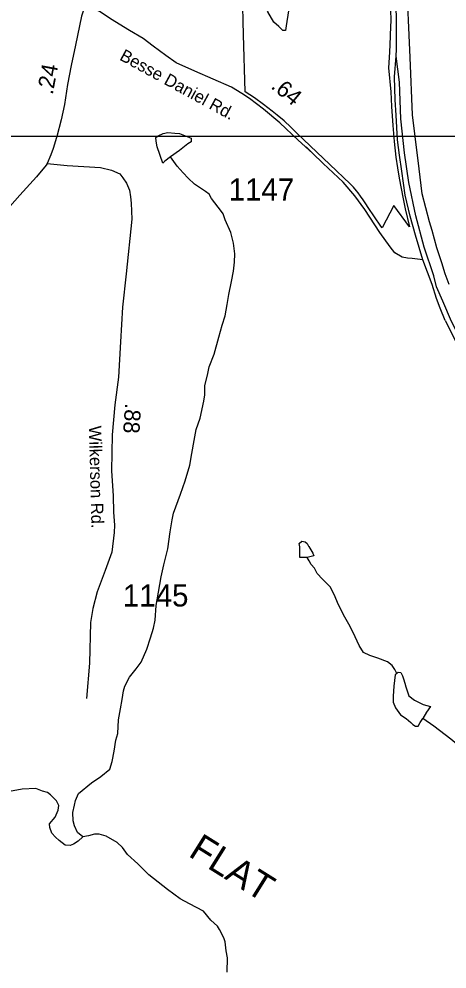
# Model space of a CAD drawing. Extents: x 1950930 to 2061844, y 904556 to 1017002.
# Drawn here: x 2002388 to 2005684, y 935305 to 942619 of the extents above; entities that cross this region are included whole.
import ezdxf

# ---------------------------------------------------------------- set-up
doc = ezdxf.new("R2010")
doc.units = 0
for name, color, linetype in [('Exist Boundary Political City Limit New', 7, 'Continuous'), ('Exist Hydrographic Creek Single Shore', 7, 'Continuous'), ('Exist Hydrographic Misc Water Feature', 7, 'Continuous'), ('Exist Hydrographic River Shore Label', 7, 'Continuous'), ('Exist Railroad Mainline', 7, 'Continuous'), ('Exist Road Primary US Attributed', 7, 'Continuous'), ('Exist Road Primary US Structure Standard Bridge CELL', 7, 'Continuous'), ('Exist Road Secondary Structure Standard Bridge Number Label', 7, 'Continuous'), ('Exist Road Secondary Type 41 Attributed', 7, 'Continuous'), ('Exist Road Secondary Type 51 Attributed', 7, 'Continuous'), ('Exist Road Secondary Type 51 Label', 7, 'Continuous'), ('Exist Road Secondary Type 51 Number Label', 7, 'Continuous'), ('Map Preparation Boundary City Limit Buffer Line', 7, 'Continuous'), ('Map Preparation Inset Cut Line', 7, 'Continuous')]:
    doc.layers.add(name, color=color, linetype=linetype)

msp = doc.modelspace()

# ---------------------------------------------------------------- linework, layer by layer
at = {"layer": 'Exist Boundary Political City Limit New'}
for points in [[(2004130.6, 942059.2), (2004117.1, 942500), (2004114, 942598.5), (2004105.5, 942956.2)], [(2005247.4, 942766.4), (2005251.5, 942610.1), (2005246.5, 942500), (2005245.8, 942484.2), (2005240.2, 942363.6), (2005234.6, 942243.3), (2005251.8, 942058.6), (2005253.4, 942001.4), (2005256.1, 941944.2), (2005266.8, 941797.5), (2005278, 941675.7), (2005291.4, 941554.1), (2005302.9, 941474.1), (2005315.8, 941394.2), (2005330.1, 941314.6), (2005345.8, 941235.3), (2005362.9, 941156.2), (2005396.2, 941017.7), (2005273.6, 941183.8), (2005183.9, 941010.8), (2005173.9, 941024.7), (2005077.1, 941166.8), (2005058.8, 941196.9), (2005049.1, 941211.7), (2005039.2, 941226.4)], [(2005039.2, 941226.4), (2005018.8, 941255.2), (2005000, 941279.8), (2004986.2, 941296.9), (2004963.4, 941323.9), (2004939.5, 941349.9), (2004782.4, 941498.4), (2004529.6, 941737.1), (2004480.4, 941786.2), (2004429.4, 941833.5), (2004376.8, 941878.9), (2004338.6, 941910), (2004270.4, 941961), (2004201.1, 942010.8), (2004130.6, 942059.2)], [(2005039.2, 941226.4), (2005018.8, 941255.2), (2005000, 941279.8), (2004986.2, 941296.9), (2004963.4, 941323.9), (2004939.5, 941349.9), (2004782.4, 941498.4), (2004529.6, 941737.1), (2004480.4, 941786.2), (2004429.4, 941833.5), (2004376.8, 941878.9), (2004338.6, 941910), (2004270.4, 941961), (2004201.1, 942010.8), (2004130.6, 942059.2)]]:
    msp.add_lwpolyline(points, dxfattribs=at)
at = {"layer": 'Exist Hydrographic Creek Single Shore'}
for points in [[(2006516.4, 935977.1), (2006468.6, 936012.9), (2006396.5, 936064.9), (2006344.4, 936100.8), (2006292.4, 936157), (2006240.5, 936232.9), (2006216.4, 936304.9), (2006168.3, 936392.9), (2006116.2, 936474.7), (2006060, 936534.6), (2006008.2, 936586.5), (2005958.2, 936674.5), (2005907.8, 936746.8), (2005866.1, 936806.7), (2005809.8, 936926.7), (2005781.7, 936994.5), (2005759.9, 937034.7), (2005713.8, 937074.4), (2005581.6, 937174.6), (2005497.5, 937234.4)], [(2002878.3, 936322.7), (2002842.1, 936288.7), (2002806.3, 936266.8), (2002782, 936254.8), (2002744.1, 936258.6), (2002696.2, 936294.7), (2002668.2, 936318.5), (2002640, 936350.6), (2002626.1, 936394.6), (2002622.1, 936422.5), (2002666.2, 936474.5), (2002689.9, 936526.5), (2002693.9, 936562.5), (2002675.9, 936598.6), (2002630, 936646.5), (2002606, 936662.4), (2002569.9, 936674.7), (2002517.8, 936694.5), (2002412, 936690.4), (2002285.8, 936666.4)], [(2003990.9, 935279.4), (2003992.9, 935391.3), (2003982.8, 935445.3), (2003976.7, 935513.4), (2003966.5, 935545.4), (2003932.7, 935609.5), (2003916.5, 935633.4), (2003864.6, 935681.4), (2003808.6, 935749.2), (2003700.5, 935805.3), (2003628.5, 935845.2), (2003532.5, 935917), (2003388.4, 936029), (2003302.3, 936115.1), (2003224.3, 936186.9), (2003184.1, 936239), (2003144.2, 936278.8), (2003058.2, 936326.9), (2003006, 936342.7), (2002970.3, 936342.8), (2002922.1, 936330.7), (2002878.3, 936322.7)]]:
    msp.add_lwpolyline(points, dxfattribs=at)
at = {"layer": 'Exist Hydrographic Misc Water Feature'}
for points in [[(2004352.2, 942894.2), (2004412.3, 942900.2), (2004452.2, 942878), (2004468.1, 942854.1), (2004468.2, 942826.2), (2004468.3, 942766.1), (2004466.2, 942744.2), (2004462.3, 942682.2), (2004444.5, 942566.1), (2004440.4, 942530.1), (2004418.5, 942530.2), (2004388.3, 942562), (2004350.2, 942594), (2004304.3, 942674), (2004282.4, 942727.9), (2004266.4, 942778.2), (2004256.1, 942834.2), (2004280.4, 942866.1), (2004312.2, 942882.2), (2004352.2, 942894.2)], [(2003554.9, 941557.6), (2003511, 941525.4), (2003494.9, 941509.6), (2003452.8, 941633.6), (2003444.9, 941677.4), (2003440.8, 941705.4), (2003460.8, 941719.4), (2003498.9, 941737.6), (2003534.9, 941745.4), (2003586.9, 941739.4), (2003623, 941737.7), (2003714.8, 941701.7), (2003714.9, 941673.8), (2003688.9, 941657.6), (2003622.9, 941605.4), (2003554.9, 941557.6)], [(2002878.3, 936322.7), (2002838.3, 936354.7), (2002816, 936406.7), (2002806, 936446.6), (2002802.1, 936510.7), (2002814.1, 936566.6), (2002822.1, 936602.8), (2002845.8, 936656.8), (2002946, 936738.8), (2003017.8, 936786.8), (2003086, 936842.9), (2003105.9, 936902.8), (2003121.7, 936982.9), (2003133.6, 937067), (2003149.7, 937118.9), (2003153.5, 937222.8), (2003169.4, 937306.8), (2003181.4, 937379.1), (2003193.6, 937447.1), (2003203.5, 937483), (2003239.4, 937551.2), (2003291.3, 937615.1), (2003327.5, 937667.2), (2003371.2, 937767), (2003399.3, 937855.1), (2003423.1, 937929.1), (2003437.2, 937991.1), (2003443.1, 938103.2), (2003463, 938207.2), (2003482.8, 938323.3), (2003502.8, 938415.4), (2003534.9, 938539.4), (2003550.7, 938671.4), (2003566.7, 938763.3), (2003578.6, 938815.2), (2003630.5, 938959.5), (2003666.5, 939063.5), (2003702.4, 939183.5), (2003718.4, 939273.4), (2003736.2, 939373.4), (2003752.4, 939457.5), (2003784.1, 939545.4), (2003812.1, 939677.4), (2003819.9, 939725.5), (2003820.1, 939797.7), (2003839.8, 939877.7), (2003852, 939941.4), (2003892, 940037.7), (2003927.9, 940169.6), (2003951.8, 940261.6), (2003975.6, 940333.7), (2003991.5, 940421.6), (2004003.6, 940497.8), (2004023.4, 940597.8), (2004039.5, 940677.9), (2004047.5, 940745.7), (2004049.4, 940809.6), (2004039.4, 940893.9), (2004019.4, 940973.7), (2003975.2, 941073.7), (2003959.3, 941117.7), (2003947.3, 941137.6), (2003871.2, 941237.7), (2003851.2, 941269.6), (2003823.1, 941289.5), (2003739, 941347.7), (2003691, 941393.7), (2003651.2, 941433.5), (2003607, 941485.6), (2003554.9, 941557.6)], [(2004606.9, 938474), (2004550.8, 938473.8), (2004550.9, 938509.9), (2004550.8, 938537.8), (2004550.8, 938553.9), (2004546.8, 938581.9), (2004566.8, 938597.9), (2004590.7, 938594.1), (2004606.9, 938581.9), (2004616.9, 938560.1), (2004618.8, 938558.1), (2004650.9, 938505.9), (2004659, 938486), (2004606.9, 938474)], [(2005297.6, 937580.2), (2005281.5, 937610.4), (2005261.5, 937642.3), (2005225.3, 937670.3), (2005151.4, 937698.4), (2005089.5, 937718), (2005041.4, 937742), (2005007.4, 937794.2), (2004977.3, 937862.1), (2004937.2, 937942.1), (2004897, 938014.1), (2004845, 938114), (2004817.2, 938182.1), (2004785, 938246.1), (2004724.9, 938306.1), (2004685.1, 938349.9), (2004663, 938390.1), (2004638.9, 938417.8), (2004622.8, 938446.1), (2004606.9, 938474)], [(2005297.6, 937580.2), (2005285.6, 937570.2), (2005273.6, 937482.2), (2005269.4, 937406.2), (2005269.7, 937358.2), (2005287.5, 937314.2), (2005325.5, 937262.2), (2005369.6, 937234.4), (2005405.7, 937202.5), (2005421.7, 937186.4), (2005441.8, 937174.5), (2005461.8, 937174.4), (2005477.8, 937202.3), (2005497.5, 937234.4)], [(2005297.6, 937580.2), (2005309.3, 937590.4), (2005329.6, 937586.4), (2005341.6, 937562.2), (2005349.6, 937538.4), (2005359.4, 937506.4), (2005367.7, 937476.3), (2005369.5, 937470.4), (2005391.5, 937408.2), (2005433.5, 937374.5), (2005501.7, 937342.3), (2005557.5, 937326.4), (2005525.8, 937282.4), (2005497.5, 937234.4)]]:
    msp.add_lwpolyline(points, dxfattribs=at)
at = {"layer": 'Exist Railroad Mainline'}
msp.add_lwpolyline([(2005702.2, 940573.4), (2005670.1, 940657.5), (2005660.1, 940689), (2005646.1, 940733.4), (2005606, 940857.4), (2005570, 940989.4), (2005550, 941057.2), (2005493.8, 941273.3), (2005469.8, 941465.2), (2005439.8, 941712.9), (2005419.4, 941881.4), (2005399.9, 942321.3), (2005371.8, 942957.4)], dxfattribs=at)
at = {"layer": 'Exist Road Primary US Attributed'}
for points in [[(2007456.1, 937590.3), (2007353.9, 937826.3), (2007189.7, 938078.2), (2006961.6, 938374.2), (2006601.3, 938888), (2006389, 939233.8), (2006081.4, 939655.9), (2005955.7, 939846.7), (2005840, 940047.3), (2005793, 940142.7), (2005718.9, 940289.5), (2005653, 940446.2), (2005603.9, 940556.5), (2005581.9, 940641.5), (2005507.7, 940862.6), (2005443.4, 941102.6), (2005389.7, 941360.7), (2005357.2, 941588.6), (2005328.4, 941849), (2005318.6, 942131.3), (2005293.6, 942331.9)], [(2005670.5, 940297.4), (2005714.3, 940212.3), (2005790, 940054.9), (2005878.6, 939893.6), (2005972.4, 939734.7), (2006051.1, 939610.5), (2006341.9, 939186.7), (2006554.2, 938840.8), (2006914.4, 938327), (2007142.5, 938031), (2007306.8, 937779.1), (2007402.4, 937559.4)]]:
    msp.add_lwpolyline(points, dxfattribs=at)
at = {"layer": 'Exist Road Secondary Structure Standard Bridge Number Label'}
for points in [[(2005293.6, 942331.9), (2005295.1, 942386.4), (2005295, 942629.3), (2005289.8, 942771.8), (2005289.8, 942905), (2005286.8, 943041.3), (2005276.9, 943279.7), (2005267.9, 943544.7), (2005251.2, 944151.8)], [(2005498.7, 940765.7), (2005441.2, 940954.9), (2005401, 941099.5), (2005363.2, 941261.5), (2005337.5, 941446.2), (2005319.3, 941570.4), (2005304.2, 941688.5), (2005292.1, 941879.3), (2005283.8, 941995.1), (2005279.2, 942172.2), (2005293.6, 942331.9)], [(2005670.5, 940297.4), (2005631.1, 940392.5), (2005602.3, 940466.7), (2005569, 940575.7), (2005498.7, 940765.7)]]:
    msp.add_lwpolyline(points, dxfattribs=at)
at = {"layer": 'Exist Road Secondary Type 41 Attributed'}
msp.add_lwpolyline([(2005498.7, 940765.7), (2005415.1, 940775.4), (2005380.6, 940776.3), (2005339.8, 940785.4), (2005282.8, 940819.1), (2005245.7, 940864.3), (2005166.5, 940975.4), (2005051.8, 941151.1), (2004975.1, 941256.5), (2004884.9, 941361.9), (2004730.7, 941505.7), (2004649.4, 941585.5), (2004599.1, 941634.2)], dxfattribs=at)
at = {"layer": 'Exist Road Secondary Type 51 Attributed'}
for points in [[(2002898.4, 942728.2), (2002868.9, 942641.7), (2002823.1, 942417.8), (2002789.3, 942261.6), (2002761.2, 942113.6), (2002737.4, 941961.6), (2002713.4, 941841.7), (2002679.5, 941712.9), (2002677.5, 941705.6), (2002649.6, 941621.5), (2002631.6, 941573.5), (2002604.4, 941505.4)], [(2004649.4, 941585.5), (2004537.1, 941686.8), (2004397.5, 941819.6), (2004271.1, 941923.5), (2004162.8, 942007.8), (2004102.8, 942045), (2004024.4, 942093.6), (2003743.1, 942217.8), (2003598.7, 942280.3), (2003519.7, 942336.8), (2003422.3, 942410.2), (2003343.3, 942469.6), (2003238.8, 942530.6), (2003092.5, 942619.1), (2003012, 942674), (2002898.4, 942728.2)], [(2002604.4, 941505.4), (2002597.4, 941493.7), (2002521.7, 941403), (2002393.9, 941261.3), (2002177.9, 941021.3)], [(2002604.4, 941505.4), (2002759.4, 941491.8), (2003014.3, 941474.5), (2003100.1, 941454.9), (2003163.3, 941426.3), (2003187.3, 941396.2), (2003214.4, 941354), (2003238.5, 941299.8), (2003247.5, 941248.6), (2003252, 941202), (2003258, 941078.5), (2003212.2, 940656.2), (2003184.3, 940401), (2003170.5, 940133.8), (2003154.7, 939861.9), (2003125.5, 939648.4), (2003105.7, 939416.4), (2003101.1, 939139.8), (2003113.2, 938947.7), (2003115.1, 938823.1), (2003122.7, 938722.2), (2003121.1, 938666.5), (2003103.1, 938514.4), (2003051.5, 938373.6), (2002990.7, 938208.4), (2002957.1, 938081.2), (2002937.4, 937971.5), (2002931.4, 937660.4), (2002907.5, 937388.2)]]:
    msp.add_lwpolyline(points, dxfattribs=at)
at = {"layer": 'Map Preparation Boundary City Limit Buffer Line'}
for points in [[(2004130.6, 942059.2), (2004117.1, 942500), (2004114, 942598.5), (2004105.5, 942956.2)], [(2005247.4, 942766.4), (2005251.5, 942610.1), (2005246.5, 942500), (2005245.8, 942484.2), (2005240.2, 942363.6), (2005234.6, 942243.3), (2005251.8, 942058.6), (2005253.4, 942001.4), (2005256.1, 941944.2), (2005266.8, 941797.5), (2005278, 941675.7), (2005291.4, 941554.1), (2005302.9, 941474.1), (2005315.8, 941394.2), (2005330.1, 941314.6), (2005345.8, 941235.3), (2005362.9, 941156.2), (2005396.2, 941017.7), (2005273.6, 941183.8), (2005183.9, 941010.8), (2005173.9, 941024.7), (2005077.1, 941166.8), (2005058.8, 941196.9), (2005049.1, 941211.7), (2005039.2, 941226.4)], [(2005039.2, 941226.4), (2005018.8, 941255.2), (2005000, 941279.8), (2004986.2, 941296.9), (2004963.4, 941323.9), (2004939.5, 941349.9), (2004782.4, 941498.4), (2004529.6, 941737.1), (2004480.4, 941786.2), (2004429.4, 941833.5), (2004376.8, 941878.9), (2004338.6, 941910), (2004270.4, 941961), (2004201.1, 942010.8), (2004130.6, 942059.2)]]:
    msp.add_lwpolyline(points, dxfattribs=at)
at = {"layer": 'Map Preparation Inset Cut Line'}
for p, q in [((2002679.5, 941712.9), (1996589.1, 941712.9)), ((2004107.1, 941712.9), (2002679.5, 941712.9)), ((2004515, 941712.9), (2004107.1, 941712.9)), ((2004604.9, 941712.9), (2004515, 941712.9)), ((2005311.8, 941712.9), (2004604.9, 941712.9)), ((2005352.8, 941712.9), (2005311.8, 941712.9)), ((2005357.6, 941712.9), (2005352.8, 941712.9)), ((2005439.8, 941712.9), (2005357.6, 941712.9)), ((2008887.8, 941712.9), (2005439.8, 941712.9))]:
    msp.add_line(p, q, dxfattribs=at)

# ---------------------------------------------------------------- texts
at = {"layer": 'Exist Hydrographic River Shore Label'}
msp.add_text('FLAT', height=210, rotation=327.98126, dxfattribs=at).set_placement((2003684.4, 936178.2))
at = {"layer": 'Exist Road Primary US Structure Standard Bridge CELL'}
for s, rotation, p in [('.24', 79.26472, (2002646.8, 942031.4)), ('.64', 320.57513, (2004321.1, 942090.5)), ('.88', 266.23837, (2003204.9, 939663.2))]:
    msp.add_text(s, height=125, rotation=rotation, dxfattribs=at).set_placement(p)
at = {"layer": 'Exist Road Secondary Type 51 Label'}
for s, rotation, p in [('Besse Daniel Rd.', 331.39356, (2003155.7, 942307.8)), ('Wilkerson Rd.', 271.4553, (2002925.8, 939485.8))]:
    msp.add_text(s, height=95, rotation=rotation, dxfattribs=at).set_placement(p)
at = {"layer": 'Exist Road Secondary Type 51 Number Label'}
for s, p in [('1147', (2004002, 941221.2)), ('1145', (2003187.1, 938095.5))]:
    msp.add_text(s, height=170, dxfattribs=at).set_placement(p)

doc.saveas('drawing.dxf')
